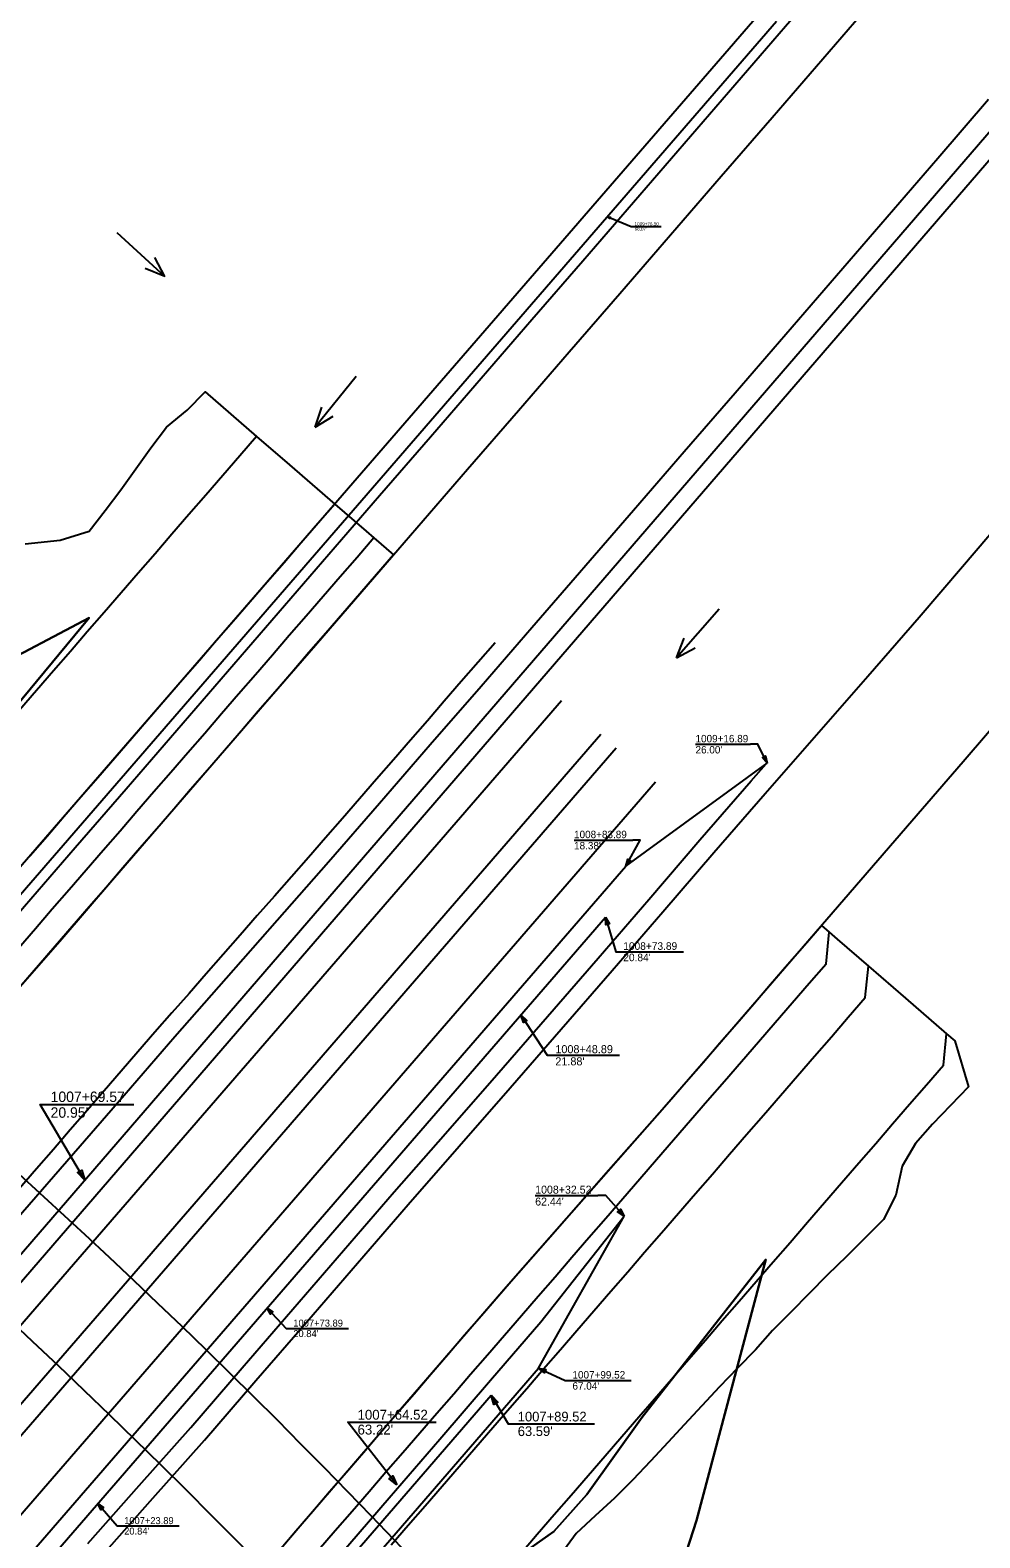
# Model space of a CAD drawing. Extents: x 1006695 to 1009377, y 1883329 to 1886115.
# Drawn here: x 1007873.9 to 1008057.5, y 1884679.4 to 1884970.9 of the extents above; entities that cross this region are included whole.
import ezdxf

# ---------------------------------------------------------------- set-up
doc = ezdxf.new("R2010")
doc.units = 0
for name, color, linetype in [('B_Hatch', 7, 'Continuous'), ('R_I-30 Information', 7, 'Continuous'), ('R_No Plot', 7, 'Continuous'), ('R_Prop Const Limits Cut', 7, 'Continuous'), ('R_Prop EOL', 7, 'Continuous'), ('R_Prop EOS I-30', 7, 'Continuous'), ('R_Prop I-30 Guardrail', 7, 'Continuous'), ('R_Water Annot', 7, 'Continuous')]:
    doc.layers.add(name, color=color, linetype=linetype)

msp = doc.modelspace()

# ---------------------------------------------------------------- linework, layer by layer
at = {"layer": 'B_Hatch'}
for points in [[(1007863.62, 1884831.18), (1007885.3, 1884857.33), (1007846.15, 1884836.71)], [(1007995.11, 1884659.21), (1008002.72, 1884682.77), (1008016.11, 1884733.22), (1007992.21, 1884702.79), (1007981.55, 1884687.82), (1007975.14, 1884680.67), (1007969.68, 1884676.79)]]:
    msp.add_lwpolyline(points, dxfattribs=at)
at = {"layer": 'R_I-30 Information'}
for p, q in [((1007780.22, 1884614.59), (1007976.64, 1884841.35)), ((1007787.78, 1884608.04), (1007984.2, 1884834.8)), ((1007790.8, 1884605.42), (1007987.22, 1884832.18)), ((1007798.36, 1884598.88), (1007994.78, 1884825.63))]:
    msp.add_line(p, q, dxfattribs=at)
for points in [[(1007870.16, 1884783.94), (1007879.97, 1884795.28), (1007889.78, 1884806.63), (1007899.59, 1884817.97), (1007909.4, 1884829.31), (1007919.21, 1884840.66), (1007929.02, 1884852.01), (1007938.82, 1884863.36), (1007948.64, 1884874.7), (1007958.46, 1884886.04), (1007968.28, 1884897.37), (1007978.1, 1884908.71), (1007987.91, 1884920.05), (1007997.72, 1884931.39), (1008007.53, 1884942.73), (1008017.34, 1884954.07), (1008027.14, 1884965.42), (1008036.95, 1884976.76)], [(1007872.88, 1884871.6), (1007879.7, 1884872.32), (1007885.3, 1884874.08), (1007888.34, 1884878.06), (1007891.39, 1884882.04), (1007894.31, 1884886.12), (1007897.23, 1884890.2), (1007900.25, 1884894.2), (1007904.2, 1884897.44), (1007907.73, 1884901), (1007917.67, 1884892.4), (1007924, 1884886.92), (1007932.79, 1884879.32), (1007938.84, 1884874.08), (1007940.35, 1884872.77), (1007944.13, 1884869.5), (1007940.86, 1884865.72), (1007937.59, 1884861.94), (1007934.32, 1884858.15), (1007931.06, 1884854.37), (1007927.79, 1884850.59), (1007924.52, 1884846.8), (1007921.25, 1884843.02), (1007917.98, 1884839.24), (1007914.71, 1884835.45), (1007911.44, 1884831.67), (1007908.17, 1884827.89), (1007904.9, 1884824.11), (1007901.63, 1884820.33), (1007898.36, 1884816.54), (1007895.09, 1884812.76), (1007891.82, 1884808.98), (1007888.54, 1884805.2), (1007885.27, 1884801.42), (1007882, 1884797.64), (1007878.73, 1884793.85), (1007875.46, 1884790.07), (1007872.19, 1884786.29)], [(1007917.67, 1884892.4), (1007914.39, 1884888.62), (1007911.1, 1884884.82), (1007907.83, 1884881.04), (1007904.56, 1884877.27), (1007901.28, 1884873.49), (1007898.01, 1884869.71), (1007894.74, 1884865.93), (1007891.47, 1884862.15), (1007888.19, 1884858.37), (1007884.92, 1884854.59), (1007881.65, 1884850.82), (1007878.38, 1884847.04), (1007875.1, 1884843.27), (1007871.83, 1884839.49)], [(1007932.79, 1884879.32), (1007929.52, 1884875.54), (1007926.24, 1884871.75), (1007922.96, 1884867.97), (1007919.69, 1884864.19), (1007916.42, 1884860.41), (1007913.14, 1884856.63), (1007909.87, 1884852.85), (1007906.6, 1884849.08), (1007903.32, 1884845.3), (1007900.05, 1884841.52), (1007896.78, 1884837.74), (1007893.51, 1884833.96), (1007890.23, 1884830.18), (1007886.96, 1884826.4), (1007883.68, 1884822.62), (1007880.41, 1884818.84), (1007877.14, 1884815.06), (1007873.86, 1884811.29)], [(1007887.67, 1884675.88), (1007897.62, 1884687.1), (1007907.58, 1884698.33), (1007917.54, 1884709.84), (1007927.35, 1884721.19), (1007937.16, 1884732.53), (1007946.97, 1884743.88), (1007956.84, 1884755.17), (1007966.71, 1884766.47), (1007976.57, 1884777.77), (1007986.4, 1884789.1), (1007996.19, 1884800.45), (1008006.09, 1884811.93), (1008015.98, 1884823.34), (1008025.92, 1884834.7), (1008035.85, 1884846.06), (1008045.78, 1884857.43), (1008054.18, 1884867.24), (1008063.97, 1884878.68)], [(1007940.35, 1884872.77), (1007937.08, 1884868.99), (1007933.8, 1884865.21), (1007930.53, 1884861.43), (1007927.26, 1884857.65), (1007923.98, 1884853.87), (1007920.71, 1884850.09), (1007917.44, 1884846.31), (1007914.16, 1884842.54), (1007910.89, 1884838.76), (1007907.62, 1884834.98), (1007904.34, 1884831.2), (1007901.07, 1884827.42), (1007897.8, 1884823.64), (1007894.52, 1884819.86), (1007891.25, 1884816.08), (1007887.97, 1884812.3), (1007884.7, 1884808.52), (1007881.43, 1884804.74), (1007878.15, 1884800.96), (1007874.88, 1884797.19), (1007871.61, 1884793.41)], [(1007963.78, 1884852.51), (1007960.5, 1884848.73), (1007957.24, 1884844.97), (1007953.96, 1884841.19), (1007950.68, 1884837.42), (1007947.4, 1884833.64), (1007944.12, 1884829.86), (1007940.85, 1884826.09), (1007937.56, 1884822.31), (1007934.28, 1884818.54), (1007930.99, 1884814.77), (1007927.7, 1884811), (1007924.4, 1884807.24), (1007921.1, 1884803.49), (1007917.79, 1884799.73), (1007914.49, 1884795.98), (1007911.19, 1884792.22), (1007907.89, 1884788.47), (1007904.59, 1884784.71), (1007901.29, 1884780.95), (1007898, 1884777.19), (1007894.72, 1884773.41), (1007891.45, 1884769.64), (1007888.17, 1884765.86), (1007884.9, 1884762.08), (1007881.62, 1884758.3), (1007878.35, 1884754.53), (1007875.07, 1884750.75), (1007871.79, 1884746.97)], [(1007916.75, 1884670.81), (1007926.47, 1884682.23), (1007936.09, 1884693.39), (1007945.88, 1884704.74), (1007955.68, 1884716.1), (1007965.47, 1884727.46), (1007975.38, 1884738.72), (1007985.29, 1884749.98), (1007995.2, 1884761.24), (1008005.04, 1884772.55), (1008014.85, 1884783.9), (1008024.65, 1884795.24), (1008034.52, 1884806.66), (1008044.4, 1884818.09), (1008054.27, 1884829.51), (1008064.12, 1884840.92)], [(1007922.01, 1884676.99), (1007925.25, 1884680.8), (1007928.5, 1884684.59), (1007931.77, 1884688.38), (1007935.03, 1884692.16), (1007938.3, 1884695.95), (1007941.56, 1884699.74), (1007944.83, 1884703.52), (1007948.1, 1884707.31), (1007951.36, 1884711.1), (1007954.63, 1884714.88), (1007957.89, 1884718.67), (1007961.16, 1884722.45), (1007964.42, 1884726.24), (1007967.71, 1884730.01), (1007971.02, 1884733.76), (1007974.32, 1884737.51), (1007977.62, 1884741.27), (1007980.92, 1884745.02), (1007984.23, 1884748.77), (1007987.53, 1884752.53), (1007990.83, 1884756.28), (1007994.14, 1884760.03), (1007997.43, 1884763.8), (1008000.71, 1884767.57), (1008003.99, 1884771.34), (1008007.26, 1884775.12), (1008010.53, 1884778.91), (1008013.8, 1884782.69), (1008017.07, 1884786.47), (1008020.34, 1884790.26), (1008023.61, 1884794.04), (1008026.88, 1884797.82), (1008026.88, 1884797.82), (1008028.4, 1884796.52), (1008029.91, 1884795.21), (1008035.96, 1884789.98), (1008043.12, 1884783.79), (1008051.09, 1884776.9), (1008052.68, 1884775.53), (1008052.67, 1884775.53), (1008055.3, 1884766.66), (1008051.83, 1884763.05), (1008048.37, 1884759.43), (1008045.07, 1884755.67), (1008042.51, 1884751.28), (1008041.3, 1884745.71), (1008038.87, 1884740.99), (1008035.34, 1884737.43), (1008031.77, 1884733.92), (1008028.02, 1884730.22), (1008024.49, 1884726.66), (1008020.97, 1884723.1), (1008017.44, 1884719.54), (1008014.13, 1884715.79), (1008010.64, 1884712.21), (1008007.17, 1884708.62), (1008003.75, 1884704.97), (1008000.35, 1884701.3), (1007997.24, 1884697.94), (1007993.82, 1884694.29), (1007990.4, 1884690.64), (1007986.84, 1884687.09), (1007983.15, 1884683.68), (1007979.45, 1884680.26), (1007976.51, 1884676.2)], [(1007929.61, 1884677.09), (1007932.86, 1884680.84), (1007936.13, 1884684.61), (1007939.4, 1884688.39), (1007942.68, 1884692.17), (1007945.95, 1884695.95), (1007949.22, 1884699.73), (1007952.5, 1884703.51), (1007955.77, 1884707.29), (1007959.05, 1884711.07), (1007962.32, 1884714.85), (1007965.59, 1884718.63), (1007968.87, 1884722.41), (1007972.1, 1884726.14), (1007975.38, 1884729.92), (1007978.65, 1884733.7), (1007981.92, 1884737.48), (1007985.2, 1884741.26), (1007988.47, 1884745.04), (1007991.74, 1884748.82), (1007995.02, 1884752.6), (1007998.29, 1884756.38), (1008001.59, 1884760.18), (1008004.86, 1884763.96), (1008008.13, 1884767.74), (1008011.42, 1884771.53), (1008014.69, 1884775.31), (1008017.97, 1884779.09), (1008021.24, 1884782.87), (1008024.51, 1884786.65), (1008027.79, 1884790.43), (1008028.39, 1884796.51), (1008028.4, 1884796.52)], [(1007943.7, 1884678.08), (1007946.98, 1884681.86), (1007950.25, 1884685.64), (1007953.52, 1884689.42), (1007956.8, 1884693.2), (1007960.07, 1884696.98), (1007963.34, 1884700.76), (1007966.62, 1884704.54), (1007969.89, 1884708.32), (1007973.17, 1884712.1), (1007976.44, 1884715.88), (1007979.61, 1884719.54), (1007982.89, 1884723.32), (1007986.16, 1884727.1), (1007989.43, 1884730.87), (1007992.7, 1884734.65), (1007995.98, 1884738.43), (1007999.25, 1884742.21), (1008002.52, 1884745.99), (1008005.8, 1884749.77), (1008009.13, 1884753.62), (1008012.4, 1884757.4), (1008015.68, 1884761.18), (1008018.99, 1884764.99), (1008022.26, 1884768.77), (1008025.53, 1884772.55), (1008028.81, 1884776.33), (1008032.08, 1884780.11), (1008035.35, 1884783.89), (1008035.96, 1884789.98), (1008035.96, 1884789.98)], [(1007968.67, 1884676.36), (1007971.94, 1884680.14), (1007975.21, 1884683.92), (1007978.49, 1884687.7), (1007981.76, 1884691.48), (1007985.04, 1884695.26), (1007988.31, 1884699.04), (1007991.59, 1884702.82), (1007994.63, 1884706.33), (1007997.91, 1884710.11), (1008001.18, 1884713.89), (1008004.44, 1884717.66), (1008007.72, 1884721.44), (1008010.99, 1884725.22), (1008014.26, 1884729), (1008017.54, 1884732.78), (1008020.81, 1884736.56), (1008024.22, 1884740.49), (1008027.49, 1884744.27), (1008030.76, 1884748.05), (1008034.12, 1884751.92), (1008037.39, 1884755.7), (1008040.66, 1884759.48), (1008043.94, 1884763.26), (1008047.21, 1884767.04), (1008050.49, 1884770.82), (1008051.09, 1884776.9), (1008051.09, 1884776.9)]]:
    msp.add_lwpolyline(points, dxfattribs=at)
at = {"layer": 'R_No Plot'}
for p, q in [((1007990.76, 1884932.99), (1007995.89, 1884932.99)), ((1008002.54, 1884832.88), (1008013.15, 1884832.88)), ((1007979.05, 1884814.35), (1007990.41, 1884814.35)), ((1007988.57, 1884792.76), (1008000.19, 1884792.76)), ((1007975.43, 1884772.74), (1007987.82, 1884772.74)), ((1007877.82, 1884763.19), (1007893.9, 1884763.19)), ((1007971.53, 1884745.61), (1007983.65, 1884745.61)), ((1007924.75, 1884719.94), (1007935.45, 1884719.94)), ((1007978.74, 1884709.88), (1007990.08, 1884709.88)), ((1007937.18, 1884701.8), (1007952.4, 1884701.8)), ((1007968.16, 1884701.47), (1007982.98, 1884701.47)), ((1007892.05, 1884681.76), (1007902.7, 1884681.76))]:
    msp.add_line(p, q, dxfattribs=at)
for points in [[(1007985.48, 1884934.89), (1007990.12, 1884932.99), (1007990.76, 1884932.99)], [(1008016.42, 1884829.24), (1008014.59, 1884832.88), (1008013.15, 1884832.88)], [(1007989.05, 1884809.28), (1007991.85, 1884814.35), (1007990.41, 1884814.35)], [(1007985.15, 1884799.43), (1007987.11, 1884792.76), (1007988.57, 1884792.76)], [(1007968.78, 1884780.53), (1007973.86, 1884772.74), (1007975.43, 1884772.74)], [(1007884.47, 1884748.62), (1007875.8, 1884763.19), (1007877.82, 1884763.19)], [(1007988.72, 1884741.6), (1007985.19, 1884745.61), (1007983.65, 1884745.61)], [(1007919.68, 1884723.85), (1007923.39, 1884719.94), (1007924.75, 1884719.94)], [(1007972.2, 1884712.26), (1007977.3, 1884709.88), (1007978.74, 1884709.88)], [(1007963.01, 1884706.99), (1007966.28, 1884701.47), (1007968.16, 1884701.47)], [(1007944.79, 1884689.7), (1007935.27, 1884701.8), (1007937.18, 1884701.8)], [(1007886.94, 1884686.05), (1007890.71, 1884681.76), (1007892.05, 1884681.76)]]:
    msp.add_lwpolyline(points, dxfattribs=at)
for points in [[(1007985.48, 1884934.89), (1007986.11, 1884934.8), (1007986, 1884934.52)], [(1008016.42, 1884829.24), (1008015.48, 1884830.33), (1008016.1, 1884830.64)], [(1007989.05, 1884809.28), (1007989.42, 1884810.67), (1007990.03, 1884810.33)], [(1007985.15, 1884799.43), (1007985.89, 1884798.17), (1007985.21, 1884797.97)], [(1007968.78, 1884780.53), (1007969.93, 1884779.47), (1007969.29, 1884779.05)], [(1007884.47, 1884748.62), (1007883.05, 1884750.05), (1007883.89, 1884750.55)], [(1007988.72, 1884741.6), (1007987.46, 1884742.47), (1007988.02, 1884742.97)], [(1007919.68, 1884723.85), (1007920.82, 1884723.12), (1007920.34, 1884722.67)], [(1007972.2, 1884712.26), (1007973.61, 1884711.99), (1007973.31, 1884711.36)], [(1007963.01, 1884706.99), (1007964.33, 1884705.66), (1007963.54, 1884705.19)], [(1007944.79, 1884689.7), (1007943.28, 1884690.87), (1007944.01, 1884691.44)], [(1007886.94, 1884686.05), (1007888.05, 1884685.29), (1007887.56, 1884684.86)]]:
    msp.add_lwpolyline(points, close=True, dxfattribs=at)
at = {"layer": 'R_Prop Const Limits Cut'}
for points in [[(1007846.15, 1884836.71), (1007885.3, 1884857.33), (1007863.62, 1884831.18)], [(1007969.68, 1884676.79), (1007975.14, 1884680.67), (1007981.55, 1884687.82), (1007992.21, 1884702.79), (1008016.11, 1884733.22), (1008002.72, 1884682.77), (1007995.11, 1884659.21)]]:
    msp.add_lwpolyline(points, dxfattribs=at)
at = {"layer": 'R_Prop EOL'}
for radius, start in [(1443.39, 37.04506), (1421.39, 35.65164)]:
    msp.add_arc((1006901.08, 1883681.49), radius, start, 53.47197, dxfattribs=at)
at = {"layer": 'R_Prop EOS I-30'}
for p, q in [((1007796.21, 1884721.79), (1008022.13, 1884982.53)), ((1007789.1, 1884632.79), (1008066.81, 1884954.51)), ((1007989.05, 1884809.28), (1008016.42, 1884829.24)), ((1007648.59, 1884416.23), (1007989.05, 1884809.28)), ((1007972.2, 1884712.26), (1007988.72, 1884741.6)), ((1007713.67, 1884413.61), (1007972.2, 1884712.26))]:
    msp.add_line(p, q, dxfattribs=at)
for points in [[(1008048.15, 1885003.65), (1008039.57, 1884994.32), (1008029.76, 1884982.98), (1008019.95, 1884971.63), (1008010.15, 1884960.28), (1008000.35, 1884948.95), (1007990.54, 1884937.61), (1007980.72, 1884926.26), (1007970.91, 1884914.92), (1007961.1, 1884903.59), (1007951.28, 1884892.26), (1007941.45, 1884880.92), (1007931.64, 1884869.58), (1007921.83, 1884858.22), (1007912.02, 1884846.87), (1007902.22, 1884835.53), (1007892.41, 1884824.18), (1007882.6, 1884812.84), (1007872.78, 1884801.5), (1007862.97, 1884790.16), (1007853.16, 1884778.81), (1007839.35, 1884762.05)], [(1008059.19, 1884957.52), (1008049.41, 1884946.15), (1008039.63, 1884934.78), (1008029.82, 1884923.41), (1008020, 1884912.07), (1008010.19, 1884900.73), (1008000.37, 1884889.39), (1007990.55, 1884878.06), (1007970.91, 1884855.39), (1007961.08, 1884844.06), (1007951.25, 1884832.73), (1007941.42, 1884821.41), (1007931.56, 1884810.09), (1007921.65, 1884798.82), (1007911.75, 1884787.56), (1007901.86, 1884776.3), (1007892.04, 1884764.98), (1007882.22, 1884753.65), (1007872.39, 1884742.32), (1007862.59, 1884731.01), (1007852.86, 1884719.61), (1007843.09, 1884708.22), (1007823.56, 1884685.45), (1007813.72, 1884674.12)], [(1007884.99, 1884678.32), (1007894.96, 1884689.56), (1007904.91, 1884700.78), (1007914.86, 1884712.29), (1007924.66, 1884723.62), (1007934.47, 1884734.96), (1007944.29, 1884746.32), (1007954.16, 1884757.62), (1007964.03, 1884768.91), (1007973.9, 1884780.21), (1007983.72, 1884791.54), (1007993.51, 1884802.88), (1008003.4, 1884814.36), (1008013.3, 1884825.77), (1008016.17, 1884829.06)], [(1007786.4, 1884505.84), (1007796.26, 1884517.26), (1007806.04, 1884528.59), (1007815.89, 1884539.87), (1007825.76, 1884551.15), (1007835.65, 1884562.46), (1007845.5, 1884573.82), (1007855.29, 1884585.22), (1007865.05, 1884596.59), (1007874.8, 1884607.91), (1007884.67, 1884619.16), (1007894.58, 1884630.47), (1007914.18, 1884653.24), (1007923.97, 1884664.63), (1007933.68, 1884676.05), (1007943.28, 1884687.18), (1007953.08, 1884698.54), (1007962.87, 1884709.9), (1007972.64, 1884721.22), (1007988.72, 1884741.6)]]:
    msp.add_lwpolyline(points, dxfattribs=at)
at = {"layer": 'R_Prop I-30 Guardrail'}
for p, q in [((1008113.17, 1885013.57), (1007737.44, 1884578.31)), ((1007805.4, 1884727.06), (1008018.22, 1884972.68)), ((1007657.79, 1884421.5), (1007985.15, 1884799.43)), ((1007717.57, 1884423.47), (1007963.01, 1884706.99))]:
    msp.add_line(p, q, dxfattribs=at)
at = {"layer": 'R_Water Annot'}
for p, q in [((1007890.61, 1884931.79), (1007899.9, 1884923.33)), ((1007899.9, 1884923.33), (1007896.11, 1884924.88)), ((1007899.9, 1884923.33), (1007898, 1884926.96)), ((1007936.89, 1884903.96), (1007928.96, 1884894.2)), ((1007928.96, 1884894.2), (1007930.3, 1884898.07)), ((1007928.96, 1884894.2), (1007932.48, 1884896.31)), ((1008007.13, 1884859), (1007998.85, 1884849.55)), ((1007998.85, 1884849.55), (1008000.33, 1884853.37)), ((1007998.85, 1884849.55), (1008002.44, 1884851.52))]:
    msp.add_line(p, q, dxfattribs=at)

# ---------------------------------------------------------------- texts
at = {"layer": 'R_No Plot'}
for s, height, p in [('1009+76.50', 0.638, (1007990.76, 1884933.15)), ("68.07'", 0.638, (1007990.76, 1884932.19)), ('1009+16.89', 1.436, (1008002.54, 1884833.24)), ("26.00'", 1.436, (1008002.54, 1884831.09)), ('1008+83.89', 1.436, (1007979.05, 1884814.71)), ("18.38'", 1.436, (1007979.05, 1884812.55)), ('1008+73.89', 1.468, (1007988.57, 1884793.12)), ("20.84'", 1.468, (1007988.57, 1884790.92)), ('1008+48.89', 1.567, (1007975.43, 1884773.13)), ("21.88'", 1.567, (1007975.43, 1884770.78)), ('1007+69.57', 2.022, (1007877.82, 1884763.7)), ("20.95'", 2.022, (1007877.82, 1884760.66)), ('1008+32.52', 1.534, (1007971.53, 1884745.99)), ("62.44'", 1.534, (1007971.53, 1884743.69)), ('1007+73.89', 1.353, (1007924.75, 1884720.28)), ("20.84'", 1.353, (1007924.75, 1884718.25)), ('1007+99.52', 1.436, (1007978.74, 1884710.24)), ("67.04'", 1.436, (1007978.74, 1884708.09)), ('1007+64.52', 1.914, (1007937.18, 1884702.28)), ('1007+89.52', 1.875, (1007968.16, 1884701.94)), ("63.22'", 1.914, (1007937.18, 1884699.41)), ("63.59'", 1.875, (1007968.16, 1884699.12)), ('1007+23.89', 1.346, (1007892.05, 1884682.09)), ("20.84'", 1.346, (1007892.05, 1884680.07))]:
    msp.add_text(s, height=height, dxfattribs=at).set_placement(p)

doc.saveas('drawing.dxf')
